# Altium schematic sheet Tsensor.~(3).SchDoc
size A4
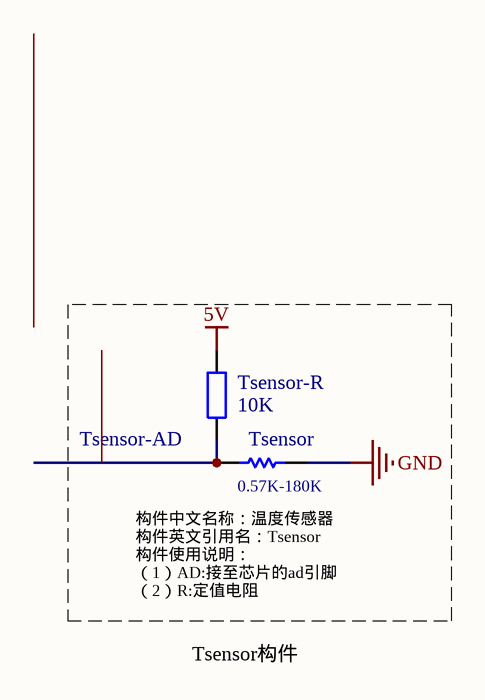
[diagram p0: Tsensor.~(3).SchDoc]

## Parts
Tsensor  0.57K-180K  [0603]
Tsensor-R  value 10K  [0603]  (hidden comment: Res2)

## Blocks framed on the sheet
Tsensor-AD: Tsensor Tsensor-R

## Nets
5V: Tsensor-R.2
GND: Tsensor.1
NetTsensor_2: Tsensor.2 Tsensor-R.1

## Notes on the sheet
- (near Tsensor) 构件中文名称：温度传感器
  构件英文引用名：Tsensor
  构件使用说明：
  （1）AD:接至芯片的ad引脚
  （2）R:定值电阻
- Tsensor构件

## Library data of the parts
Tsensor = Res1: Resistor; Value: 1K
Tsensor-R = Res2: Resistor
